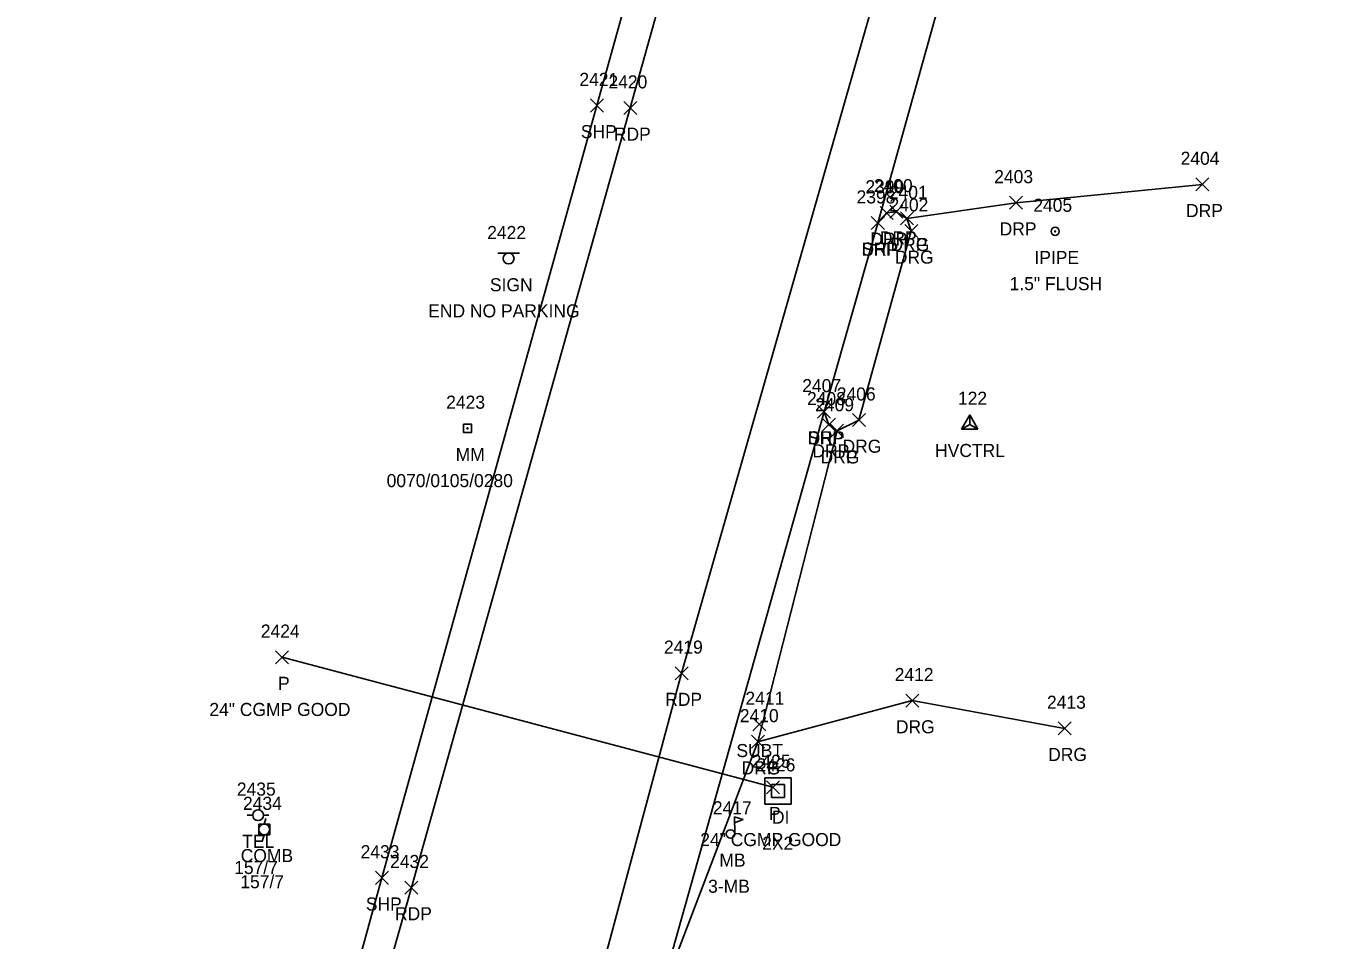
# Model space of a CAD drawing. Extents: x 1443071 to 1445292, y 614024 to 622563.
# Drawn here: x 1444199 to 1444397, y 620900.9 to 621040.9 of the extents above; entities that cross this region are included whole.
import ezdxf

# ---------------------------------------------------------------- set-up
doc = ezdxf.new("R2010")
doc.units = 0
for name, color, linetype in [('C_A', 7, 'Continuous'), ('C_I', 7, 'Continuous'), ('CPSM', 7, 'Continuous'), ('D_A', 7, 'Continuous'), ('D_C', 7, 'Continuous'), ('D_I', 7, 'Continuous'), ('D_TIC', 7, 'Continuous'), ('DCP', 7, 'Continuous'), ('DS', 7, 'Continuous'), ('L_A', 7, 'Continuous'), ('L_C', 7, 'Continuous'), ('L_I', 7, 'Continuous'), ('LMB', 7, 'Continuous'), ('M_A', 7, 'Continuous'), ('M_C', 7, 'Continuous'), ('M_I', 7, 'Continuous'), ('MPIP', 7, 'Continuous'), ('P_A', 7, 'Continuous'), ('P_I', 7, 'Continuous'), ('P_TIC', 7, 'Continuous'), ('PET', 7, 'Continuous'), ('PSP', 7, 'Continuous'), ('R_A', 7, 'Continuous'), ('R_I', 7, 'Continuous'), ('R_TIC', 7, 'Continuous'), ('RDG', 7, 'Continuous'), ('RDP', 7, 'Continuous'), ('S_A', 7, 'Continuous'), ('S_C', 7, 'Continuous'), ('S_I', 7, 'Continuous'), ('SRM', 7, 'Continuous'), ('SSGN', 7, 'Continuous'), ('U_A', 7, 'Continuous'), ('U_C', 7, 'Continuous'), ('U_I', 7, 'Continuous'), ('U_TIC', 7, 'Continuous'), ('UP', 7, 'Continuous')]:
    doc.layers.add(name, color=color, linetype=linetype)

msp = doc.modelspace()

# ---------------------------------------------------------------- linework, layer by layer
at = {"layer": 'CPSM'}
for p, q in [((1444342.28, 620979.18), (1444343.53, 620981.34)), ((1444342.28, 620979.18), (1444343.53, 620979.9)), ((1444344.78, 620979.18), (1444343.53, 620981.34)), ((1444343.53, 620979.9), (1444343.53, 620981.34)), ((1444343.53, 620979.9), (1444343.53, 620979.9)), ((1444343.53, 620979.9), (1444344.78, 620979.18)), ((1444342.28, 620979.18), (1444344.78, 620979.18))]:
    msp.add_line(p, q, dxfattribs=at)
at = {"layer": 'D_TIC'}
for points in [[(1444237.22, 620943.25), (1444239.22, 620945.25)], [(1444239.22, 620943.25), (1444237.22, 620945.25)], [(1444312.4, 620923.33), (1444314.4, 620925.33)], [(1444314.4, 620923.33), (1444312.4, 620925.33)]]:
    msp.add_lwpolyline(points, dxfattribs=at)
at = {"layer": 'DCP'}
msp.add_lwpolyline([(1444238.22, 620944.25), (1444313.4, 620924.33)], dxfattribs=at)
at = {"layer": 'DS'}
for p, q in [((1444312.17, 620925.77), (1444316.17, 620925.77)), ((1444312.17, 620921.77), (1444312.17, 620925.77)), ((1444313.17, 620922.77), (1444313.17, 620924.77)), ((1444313.17, 620924.77), (1444315.17, 620924.77)), ((1444315.17, 620924.77), (1444315.17, 620922.77)), ((1444316.17, 620925.77), (1444316.17, 620921.77)), ((1444315.17, 620922.77), (1444313.17, 620922.77)), ((1444314.18, 620923.77), (1444314.18, 620923.77)), ((1444314.18, 620923.77), (1444314.18, 620923.77)), ((1444316.17, 620921.77), (1444312.17, 620921.77))]:
    msp.add_line(p, q, dxfattribs=at)
at = {"layer": 'LMB'}
for p, q in [((1444307.53, 620919.79), (1444308.82, 620919.41)), ((1444307.54, 620917.2), (1444307.53, 620919.79)), ((1444307.53, 620918.89), (1444308.82, 620919.4)), ((1444306.88, 620917.19), (1444306.88, 620917.19))]:
    msp.add_line(p, q, dxfattribs=at)
msp.add_circle((1444306.88, 620917.19), 0.656, dxfattribs=at)
at = {"layer": 'MPIP'}
for radius in [0.625, 0.0833]:
    msp.add_circle((1444356.61, 621009.44), radius, dxfattribs=at)
at = {"layer": 'P_TIC'}
for points in [[(1444285.44, 621027.71), (1444287.44, 621029.71)], [(1444287.44, 621027.71), (1444285.44, 621029.71)], [(1444290.55, 621027.33), (1444292.55, 621029.33)], [(1444292.55, 621027.33), (1444290.55, 621029.33)], [(1444328.46, 621009.72), (1444330.46, 621011.72)], [(1444330.46, 621009.72), (1444328.46, 621011.72)], [(1444320.22, 620980.83), (1444322.22, 620982.83)], [(1444322.22, 620980.83), (1444320.22, 620982.83)], [(1444298.41, 620940.8), (1444300.41, 620942.8)], [(1444300.41, 620940.8), (1444298.41, 620942.8)], [(1444252.5, 620909.47), (1444254.5, 620911.47)], [(1444254.5, 620909.47), (1444252.5, 620911.47)], [(1444257.02, 620907.98), (1444259.02, 620909.98)], [(1444259.02, 620907.98), (1444257.02, 620909.98)]]:
    msp.add_lwpolyline(points, dxfattribs=at)
at = {"layer": 'PET'}
for points in [[(1444393.99, 621275.61), (1444360.23, 621155.32), (1444345.74, 621103.98), (1444299.41, 620941.8), (1444273.27, 620844.52), (1444244.09, 620730.97), (1444221.37, 620651.37), (1444196.75, 620548.06), (1444177.44, 620486.23), (1444161.6, 620423.84), (1444143.45, 620356.38), (1444122.97, 620254.68), (1444105.94, 620160.17), (1444094.56, 620089.52), (1444083.91, 620011.71), (1444077.6, 619958.52), (1444073.05, 619913.75)], [(1444350.41, 621238.76), (1444319.14, 621126.97), (1444291.55, 621028.33), (1444258.02, 620908.98), (1444225.45, 620794.19), (1444210.22, 620737.59), (1444176.75, 620619.09), (1444153.1, 620523.45), (1444139.28, 620467.17), (1444131.97, 620435.45), (1444113.12, 620363.38), (1444103.37, 620315.76), (1444093.47, 620268.1), (1444084.86, 620222.29), (1444073.72, 620159.9), (1444065.08, 620092.83), (1444054.27, 620016.44), (1444048.57, 619960.86), (1444043.42, 619916.17), (1444073.05, 619913.75)]]:
    msp.add_lwpolyline(points, dxfattribs=at)
at = {"layer": 'PSP'}
for points in [[(1444397.04, 621252.99), (1444383.69, 621203.04), (1444369.27, 621153.38), (1444354.52, 621100.43), (1444340.93, 621051.88), (1444329.46, 621010.72), (1444321.22, 620981.83), (1444295.58, 620890.64), (1444282.49, 620842.68), (1444250.85, 620729.5), (1444228.91, 620648.98), (1444202.76, 620547.52)], [(1444345.99, 621239.2), (1444324.65, 621163.68), (1444307.34, 621103.94), (1444286.44, 621028.71), (1444253.5, 620910.47), (1444226.49, 620812.23), (1444217.75, 620781.55), (1444205.71, 620738.94), (1444173.15, 620620.17), (1444162.97, 620582.35)]]:
    msp.add_lwpolyline(points, dxfattribs=at)
at = {"layer": 'R_TIC'}
for points in [[(1444378.17, 621015.63), (1444380.17, 621017.63)], [(1444380.17, 621015.63), (1444378.17, 621017.63)], [(1444329.82, 621011.27), (1444331.82, 621013.27)], [(1444331.82, 621011.27), (1444329.82, 621013.27)], [(1444331.27, 621011.45), (1444333.27, 621013.45)], [(1444333.27, 621011.45), (1444331.27, 621013.45)], [(1444349.62, 621012.82), (1444351.62, 621014.82)], [(1444351.62, 621012.82), (1444349.62, 621014.82)], [(1444328.46, 621009.72), (1444330.46, 621011.72)], [(1444330.46, 621009.72), (1444328.46, 621011.72)], [(1444332.91, 621010.42), (1444334.91, 621012.42)], [(1444334.91, 621010.42), (1444332.91, 621012.42)], [(1444332.91, 621010.42), (1444334.91, 621012.42)], [(1444334.91, 621010.42), (1444332.91, 621012.42)], [(1444333.57, 621008.5), (1444335.57, 621010.5)], [(1444335.57, 621008.5), (1444333.57, 621010.5)], [(1444320.22, 620980.83), (1444322.22, 620982.83)], [(1444322.22, 620980.83), (1444320.22, 620982.83)], [(1444320.95, 620978.84), (1444322.95, 620980.84)], [(1444322.95, 620978.84), (1444320.95, 620980.84)], [(1444322.21, 620977.91), (1444324.21, 620979.91)], [(1444324.21, 620977.91), (1444322.21, 620979.91)], [(1444322.21, 620977.91), (1444324.21, 620979.91)], [(1444324.21, 620977.91), (1444322.21, 620979.91)], [(1444325.56, 620979.55), (1444327.56, 620981.55)], [(1444327.56, 620979.55), (1444325.56, 620981.55)], [(1444333.73, 620936.6), (1444335.73, 620938.6)], [(1444335.73, 620936.6), (1444333.73, 620938.6)], [(1444357.05, 620932.36), (1444359.05, 620934.36)], [(1444359.05, 620932.36), (1444357.05, 620934.36)], [(1444310.1, 620930.3), (1444312.1, 620932.3)], [(1444312.1, 620930.3), (1444310.1, 620932.3)], [(1444310.1, 620930.3), (1444312.1, 620932.3)], [(1444312.1, 620930.3), (1444310.1, 620932.3)]]:
    msp.add_lwpolyline(points, dxfattribs=at)
at = {"layer": 'RDG'}
for points in [[(1444333.91, 621011.42), (1444334.57, 621009.5), (1444326.56, 620980.55), (1444323.21, 620978.91)], [(1444311.1, 620931.3), (1444334.73, 620937.6), (1444358.05, 620933.36)]]:
    msp.add_lwpolyline(points, dxfattribs=at)
at = {"layer": 'RDP'}
for points in [[(1444329.46, 621010.72), (1444330.82, 621012.27), (1444332.27, 621012.45), (1444333.91, 621011.42), (1444350.62, 621013.82), (1444379.17, 621016.63)], [(1444321.22, 620981.83), (1444321.95, 620979.84), (1444323.21, 620978.91), (1444311.1, 620931.3), (1444295.58, 620890.64)]]:
    msp.add_lwpolyline(points, dxfattribs=at)
at = {"layer": 'SRM'}
msp.add_lwpolyline([(1444265.99, 620979.91), (1444267.24, 620979.91), (1444267.24, 620978.66), (1444265.99, 620978.66)], close=True, dxfattribs=at)
msp.add_circle((1444266.61, 620979.29), 0.0833, dxfattribs=at)
at = {"layer": 'SSGN'}
for p, q in [((1444271.26, 621006.12), (1444274.6, 621006.12)), ((1444272.91, 621005.29), (1444272.91, 621005.29))]:
    msp.add_line(p, q, dxfattribs=at)
msp.add_circle((1444272.91, 621005.29), 0.833, dxfattribs=at)
at = {"layer": 'U_TIC'}
for points in [[(1444310.31, 620932.96), (1444312.31, 620934.96)], [(1444312.31, 620932.96), (1444310.31, 620934.96)]]:
    msp.add_lwpolyline(points, dxfattribs=at)
at = {"layer": 'UP'}
for p, q in [((1444232.89, 620920.05), (1444233.71, 620920.05)), ((1444234.55, 620920.06), (1444234.55, 620920.06)), ((1444234.66, 620917.05), (1444234.66, 620918.71)), ((1444234.66, 620918.71), (1444236.33, 620918.71)), ((1444236.21, 620920.06), (1444235.38, 620920.06)), ((1444235.38, 620920.06), (1444235.38, 620920.06)), ((1444235.74, 620919.55), (1444235.49, 620918.71)), ((1444236.21, 620920.06), (1444236.21, 620920.06)), ((1444236.33, 620918.71), (1444236.33, 620917.05)), ((1444236.33, 620917.05), (1444234.66, 620917.05)), ((1444235.24, 620916.21), (1444235.49, 620917.05)), ((1444235.49, 620917.88), (1444235.49, 620917.88))]:
    msp.add_line(p, q, dxfattribs=at)
for centre in [(1444234.55, 620920.06), (1444235.49, 620917.88)]:
    msp.add_circle(centre, 0.833, dxfattribs=at)

# ---------------------------------------------------------------- texts
at = {"layer": 'C_A'}
msp.add_text('HVCTRL', height=2, dxfattribs=at).set_placement((1444338.22, 620974.9))
at = {"layer": 'C_I'}
msp.add_text('122', height=2, dxfattribs=at).set_placement((1444341.73, 620982.9))
at = {"layer": 'D_A'}
for s, p in [('P', (1444237.6, 620939.25)), ('P', (1444312.78, 620919.33)), ('DI', (1444313.24, 620918.77))]:
    msp.add_text(s, height=2, dxfattribs=at).set_placement(p)
at = {"layer": 'D_C'}
for s, p in [('24" CGMP GOOD', (1444227.08, 620935.25)), ('24" CGMP GOOD', (1444302.26, 620915.33)), ('2X2', (1444311.75, 620914.77))]:
    msp.add_text(s, height=2, dxfattribs=at).set_placement(p)
at = {"layer": 'D_I'}
for s, p in [('2424', (1444234.96, 620947.25)), ('2425', (1444310.14, 620927.33)), ('2426', (1444310.87, 620926.77))]:
    msp.add_text(s, height=2, dxfattribs=at).set_placement(p)
at = {"layer": 'L_A'}
msp.add_text('MB', height=2, dxfattribs=at).set_placement((1444305.19, 620912.19))
at = {"layer": 'L_C'}
msp.add_text('3-MB', height=2, dxfattribs=at).set_placement((1444303.47, 620908.19))
at = {"layer": 'L_I'}
msp.add_text('2417', height=2, dxfattribs=at).set_placement((1444304.19, 620920.19))
at = {"layer": 'M_A'}
msp.add_text('IPIPE', height=2, dxfattribs=at).set_placement((1444353.44, 621004.44))
at = {"layer": 'M_C'}
msp.add_text('1.5" FLUSH', height=2, dxfattribs=at).set_placement((1444349.64, 621000.44))
at = {"layer": 'M_I'}
msp.add_text('2405', height=2, dxfattribs=at).set_placement((1444353.27, 621012.44))
at = {"layer": 'P_A'}
for s, p in [('SHP', (1444283.97, 621023.71)), ('RDP', (1444289.03, 621023.33)), ('SHP', (1444327, 621005.72)), ('SHP', (1444318.75, 620976.83)), ('RDP', (1444296.89, 620936.8)), ('SHP', (1444251.04, 620905.47)), ('RDP', (1444255.51, 620903.98))]:
    msp.add_text(s, height=2, dxfattribs=at).set_placement(p)
at = {"layer": 'P_I'}
for s, p in [('2421', (1444283.75, 621031.71)), ('2420', (1444288.2, 621031.33)), ('2398', (1444326.2, 621013.72)), ('2407', (1444317.88, 620984.83)), ('2419', (1444296.7, 620944.8)), ('2433', (1444250.24, 620913.47)), ('2432', (1444254.76, 620911.98))]:
    msp.add_text(s, height=2, dxfattribs=at).set_placement(p)
at = {"layer": 'R_A'}
for s, p in [('DRP', (1444376.66, 621011.63)), ('DRP', (1444329.76, 621007.45)), ('DRP', (1444348.11, 621008.82)), ('DRP', (1444326.95, 621005.72)), ('DRP', (1444328.31, 621007.27)), ('DRG', (1444331.4, 621006.42)), ('DRP', (1444331.4, 621006.42)), ('DRG', (1444332.06, 621004.5)), ('DRP', (1444318.71, 620976.83)), ('DRP', (1444319.44, 620974.84)), ('DRG', (1444320.7, 620973.91)), ('DRP', (1444320.7, 620973.91)), ('DRG', (1444324.05, 620975.55)), ('DRG', (1444332.22, 620932.6)), ('DRG', (1444355.54, 620928.36)), ('DRG', (1444308.59, 620926.3)), ('DRP', (1444308.59, 620926.3))]:
    msp.add_text(s, height=2, dxfattribs=at).set_placement(p)
at = {"layer": 'R_I'}
for s, p in [('2404', (1444375.83, 621019.63)), ('2399', (1444327.55, 621015.27)), ('2400', (1444328.85, 621015.45)), ('2403', (1444347.28, 621016.82)), ('2398', (1444326.2, 621013.72)), ('2401', (1444331.14, 621014.42)), ('2401', (1444331.14, 621014.42)), ('2402', (1444331.24, 621012.5)), ('2407', (1444317.88, 620984.83)), ('2406', (1444323.17, 620983.55)), ('2408', (1444318.61, 620982.84)), ('2409', (1444319.86, 620981.91)), ('2409', (1444319.86, 620981.91)), ('2412', (1444332.04, 620940.6)), ('2413', (1444355.36, 620936.36)), ('2410', (1444308.32, 620934.3)), ('2410', (1444308.32, 620934.3))]:
    msp.add_text(s, height=2, dxfattribs=at).set_placement(p)
at = {"layer": 'S_A'}
for s, p in [('SIGN', (1444270.05, 621000.27)), ('MM', (1444264.8, 620974.29))]:
    msp.add_text(s, height=2, dxfattribs=at).set_placement(p)
at = {"layer": 'S_C'}
for s, p in [('END NO PARKING', (1444260.6, 620996.27)), ('0070/0105/0280', (1444254.23, 620970.29))]:
    msp.add_text(s, height=2, dxfattribs=at).set_placement(p)
at = {"layer": 'S_I'}
for s, p in [('2422', (1444269.63, 621008.27)), ('2423', (1444263.35, 620982.29))]:
    msp.add_text(s, height=2, dxfattribs=at).set_placement(p)
at = {"layer": 'U_A'}
for s, p in [('SUBT', (1444307.8, 620928.96)), ('TEL', (1444232.11, 620915.06)), ('COMB', (1444231.88, 620912.88))]:
    msp.add_text(s, height=2, dxfattribs=at).set_placement(p)
at = {"layer": 'U_C'}
for p in [(1444230.88, 620911.06), (1444231.82, 620908.88)]:
    msp.add_text('157/7', height=2, dxfattribs=at).set_placement(p)
at = {"layer": 'U_I'}
for s, p in [('2411', (1444309.18, 620936.96)), ('2435', (1444231.29, 620923.06)), ('2434', (1444232.23, 620920.88))]:
    msp.add_text(s, height=2, dxfattribs=at).set_placement(p)

doc.saveas('drawing.dxf')
